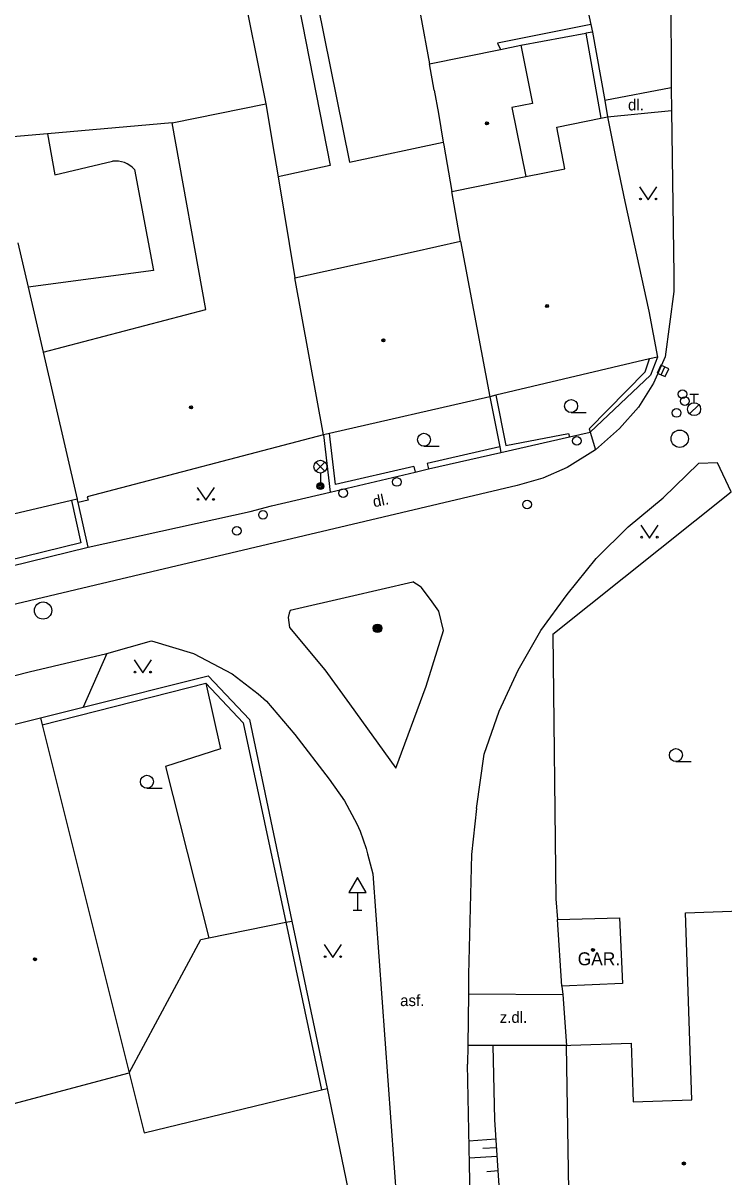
# Model space of a CAD drawing. Extents: x -596024 to -594475, y -1163820 to -1161957.
# Drawn here: x -595918.9 to -595878.3, y -1162976.4 to -1162909.7 of the extents above; entities that cross this region are included whole.
import ezdxf

# ---------------------------------------------------------------- set-up
doc = ezdxf.new("R2010")
doc.units = 0
for name, color, linetype in [('Level 10', 7, 'Continuous'), ('Level 11', 7, 'Continuous'), ('Level 14', 7, 'Continuous'), ('Level 15', 7, 'Continuous'), ('Level 25', 7, 'Continuous'), ('Level 27', 7, 'Continuous'), ('Level 28', 7, 'Continuous'), ('Level 33', 7, 'Continuous'), ('Level 34', 7, 'Continuous'), ('Level 36', 7, 'Continuous'), ('Level 39', 7, 'Continuous'), ('Level 40', 7, 'Continuous'), ('Level 41', 7, 'Continuous'), ('Level 5', 7, 'Continuous'), ('Level 7', 7, 'Continuous'), ('Level 8', 7, 'Continuous')]:
    doc.layers.add(name, color=color, linetype=linetype)

msp = doc.modelspace()

# ---------------------------------------------------------------- linework, layer by layer
at = {"layer": 'Level 10'}
for points in [[(-595881.44, -1162901.97), (-595881.4, -1162913.49)], [(-595881.4, -1162913.49), (-595881.38, -1162914.79)], [(-595881.38, -1162914.79), (-595881.25, -1162924.29)], [(-595881.25, -1162924.29), (-595881.24, -1162925.26), (-595881.74, -1162929.04)], [(-595881.74, -1162929.04), (-595882.41, -1162930.55), (-595883.29, -1162931.94), (-595884.38, -1162933.18), (-595885.77, -1162934.41)], [(-595885.77, -1162934.41), (-595887.41, -1162935.44), (-595888.81, -1162936.05)], [(-595877.93, -1162936.84), (-595878.71, -1162935.16), (-595879.82, -1162935.2), (-595881.85, -1162937.19)], [(-595888.81, -1162936.05), (-595890.3, -1162936.47), (-595913.55, -1162941.97)], [(-595892.66, -1162955.15), (-595892.21, -1162952), (-595891.34, -1162949.52), (-595890.24, -1162947.14), (-595888.94, -1162944.86), (-595887.41, -1162942.78), (-595885.74, -1162940.7), (-595883.88, -1162938.86), (-595881.85, -1162937.19)], [(-595913.55, -1162941.97), (-595928.03, -1162945.39)], [(-595903.434, -1162943.703), (-595903.477, -1162943.852), (-595903.553, -1162944.111), (-595903.464, -1162944.677), (-595901.427, -1162947.122), (-595900, -1162949.093), (-595897.312, -1162952.807), (-595895.563, -1162948.076), (-595894.569, -1162944.856), (-595894.828, -1162943.743), (-595895.315, -1162943.057), (-595895.851, -1162942.352), (-595895.913, -1162942.314), (-595896.34, -1162942.05)], [(-595896.338, -1162942.054), (-595900, -1162942.905), (-595903.434, -1162943.703)], [(-595914.04, -1162946.18), (-595911.45, -1162945.45)], [(-595911.45, -1162945.45), (-595909.02, -1162946.19), (-595906.78, -1162947.36), (-595905.27, -1162948.51), (-595904.8, -1162948.94), (-595903.15, -1162950.87)], [(-595918.53, -1162947.25), (-595914.04, -1162946.18)], [(-595926.31, -1162949.23), (-595918.53, -1162947.25)], [(-595903.15, -1162950.87), (-595901.17, -1162953.45)], [(-595901.17, -1162953.45), (-595900.29, -1162954.7), (-595899.58, -1162956.04), (-595899.39, -1162956.46), (-595899.03, -1162957.46), (-595898.95, -1162957.77), (-595898.65, -1162958.93)], [(-595892.66, -1162955.15), (-595892.94, -1162957.799), (-595893.11, -1162964.74)], [(-595898.65, -1162958.93), (-595897.09, -1162980.42)], [(-595893.11, -1162964.74), (-595893.12, -1162965.87), (-595893.16, -1162968.85), (-595893.17, -1162969.93)], [(-595892.69, -1162984.19), (-595893, -1162978.7), (-595893.06, -1162975.7), (-595893.17, -1162969.93)]]:
    msp.add_lwpolyline(points, dxfattribs=at)
at = {"layer": 'Level 11'}
for points in [[(-595907.81, -1162899.59), (-595904.83, -1162914.4)], [(-595904.74, -1162899.49), (-595901.11, -1162917.98), (-595904.13, -1162918.63)], [(-595903.7, -1162899.45), (-595899.99, -1162917.78), (-595894.58, -1162916.62)], [(-595895.89, -1162909.28), (-595895.38, -1162912.1)], [(-595886.04, -1162909.83), (-595891.43, -1162910.9), (-595891.26, -1162911.26)], [(-595890.09, -1162911.02), (-595886.34, -1162910.33)], [(-595881.4, -1162913.49), (-595885.24, -1162914.22)], [(-595885.07, -1162915.16), (-595881.38, -1162914.79)], [(-595910.26, -1162915.51), (-595917.46, -1162916.14), (-595920.37, -1162916.4)], [(-595917.46, -1162916.14), (-595917.04, -1162918.52), (-595913.71, -1162917.73)], [(-595912.44, -1162918.2), (-595911.33, -1162924.04), (-595918.58, -1162925.01)], [(-595882.18, -1162929.05), (-595882.6, -1162930.1)], [(-595891.88, -1162931.34), (-595891.31, -1162934.23)], [(-595901.5, -1162933.54), (-595901.11, -1162936.85)], [(-595886.08, -1162933.39), (-595885.77, -1162934.41)], [(-595891.31, -1162934.23), (-595891.24, -1162934.57)], [(-595895.42, -1162935.51), (-595891.24, -1162934.57)], [(-595901.11, -1162936.85), (-595896.2, -1162935.7)], [(-595904.51, -1162937.64), (-595901.11, -1162936.85)], [(-595916.07, -1162937.34), (-595915.54, -1162939.79), (-595927.34, -1162942.68), (-595927.97, -1162940.13)], [(-595915.11, -1162940.04), (-595915.68, -1162937.45)], [(-595928.31, -1162940.21), (-595927.6, -1162943.1), (-595915.11, -1162940.04)], [(-595914.04, -1162946.18), (-595915.4, -1162949.29)], [(-595908.3, -1162947.91), (-595907.45, -1162951.7), (-595910.63, -1162952.71), (-595908.14, -1162962.63)], [(-595893.12, -1162965.87), (-595887.67, -1162965.89)], [(-595887.44, -1162968.84), (-595891.69, -1162968.85), (-595893.16, -1162968.85)]]:
    msp.add_lwpolyline(points, dxfattribs=at)
msp.add_arc((-595913.511, -1162919.144), 1.428, 41.38561, 97.9975, dxfattribs=at)
at = {"layer": 'Level 14'}
msp.add_lwpolyline([(-595886.28, -1162985.95), (-595890.76, -1162985.73), (-595891.6, -1162973.14), (-595891.69, -1162968.85)], dxfattribs=at)
at = {"layer": 'Level 15'}
for points in [[(-595891.53, -1162974.26), (-595893.09, -1162974.37)], [(-595891.49, -1162974.76), (-595892.28, -1162974.81)], [(-595891.46, -1162975.26), (-595893.07, -1162975.37)], [(-595892.05, -1162976.13), (-595891.39, -1162976.08)]]:
    msp.add_lwpolyline(points, dxfattribs=at)
at = {"layer": 'Level 25'}
for radius in [0.25, 0.2, 0.15, 0.1, 0.05]:
    msp.add_circle((-595898.37, -1162944.73), radius, dxfattribs=at)
at = {"layer": 'Level 27'}
msp.add_line((-595881.971, -1162930.079), (-595881.769, -1162929.621), dxfattribs=at)
msp.add_lwpolyline([(-595881.742, -1162930.18), (-595881.54, -1162929.722), (-595881.998, -1162929.52), (-595882.2, -1162929.978)], close=True, dxfattribs=at)
for centre in [(-595880.9, -1162933.77), (-595917.72, -1162943.7)]:
    msp.add_circle(centre, 0.5, dxfattribs=at)
at = {"layer": 'Level 28'}
for p, q in [((-595880.32, -1162931.185), (-595879.82, -1162931.185)), ((-595880.07, -1162931.685), (-595880.07, -1162931.185)), ((-595880.328, -1162932.332), (-595879.798, -1162931.802))]:
    msp.add_line(p, q, dxfattribs=at)
for centre, radius in [((-595880.74, -1162931.19), 0.25), ((-595880.61, -1162931.59), 0.25), ((-595881.08, -1162932.28), 0.25), ((-595880.07, -1162932.06), 0.375), ((-595886.85, -1162933.89), 0.25), ((-595897.26, -1162936.27), 0.25), ((-595900.37, -1162936.91), 0.25), ((-595889.73, -1162937.57), 0.25), ((-595905, -1162938.17), 0.25), ((-595906.52, -1162939.09), 0.25)]:
    msp.add_circle(centre, radius, dxfattribs=at)
at = {"layer": 'Level 33'}
for p, q in [((-595901.945, -1162935.65), (-595901.415, -1162935.12)), ((-595901.945, -1162935.12), (-595901.415, -1162935.65)), ((-595901.68, -1162935.76), (-595901.68, -1162936.51))]:
    msp.add_line(p, q, dxfattribs=at)
for centre, radius in [((-595901.68, -1162935.385), 0.375), ((-595901.68, -1162936.51), 0.2), ((-595901.68, -1162936.51), 0.145), ((-595901.68, -1162936.51), 0.0876)]:
    msp.add_circle(centre, radius, dxfattribs=at)
at = {"layer": 'Level 34'}
for p, q in [((-595899.54, -1162960.002), (-595899.54, -1162961.02)), ((-595899.79, -1162961.02), (-595899.29, -1162961.02))]:
    msp.add_line(p, q, dxfattribs=at)
msp.add_lwpolyline([(-595900.04, -1162960.002), (-595899.04, -1162960.002), (-595899.54, -1162959.136)], close=True, dxfattribs=at)
at = {"layer": 'Level 36'}
for p, q in [((-595887.18, -1162932.255), (-595886.305, -1162932.255)), ((-595895.69, -1162934.205), (-595894.815, -1162934.205)), ((-595881.12, -1162952.435), (-595880.245, -1162952.435)), ((-595911.71, -1162953.975), (-595910.835, -1162953.975))]:
    msp.add_line(p, q, dxfattribs=at)
for points in [[(-595883.22, -1162919.21), (-595882.72, -1162919.96), (-595882.22, -1162919.21)], [(-595908.81, -1162936.58), (-595908.31, -1162937.33), (-595907.81, -1162936.58)], [(-595883.15, -1162938.76), (-595882.65, -1162939.51), (-595882.15, -1162938.76)], [(-595912.45, -1162946.56), (-595911.95, -1162947.31), (-595911.45, -1162946.56)], [(-595901.46, -1162963.01), (-595900.96, -1162963.76), (-595900.46, -1162963.01)]]:
    msp.add_lwpolyline(points, dxfattribs=at)
for centre, radius in [((-595883.17, -1162919.91), 0.05), ((-595882.271, -1162919.91), 0.05), ((-595887.18, -1162931.88), 0.375), ((-595895.69, -1162933.83), 0.375), ((-595908.76, -1162937.28), 0.05), ((-595907.861, -1162937.28), 0.05), ((-595883.1, -1162939.46), 0.05), ((-595882.201, -1162939.46), 0.05), ((-595912.4, -1162947.26), 0.05), ((-595911.501, -1162947.26), 0.05), ((-595881.12, -1162952.06), 0.375), ((-595911.71, -1162953.6), 0.375), ((-595901.41, -1162963.71), 0.05), ((-595900.511, -1162963.71), 0.05)]:
    msp.add_circle(centre, radius, dxfattribs=at)
at = {"layer": 'Level 39'}
for centre, radius in [((-595892.05, -1162915.54), 0.09), ((-595892.05, -1162915.54), 0.0398), ((-595888.57, -1162926.1), 0.09), ((-595888.57, -1162926.1), 0.0398), ((-595898.04, -1162928.08), 0.09), ((-595898.04, -1162928.08), 0.0398), ((-595909.16, -1162931.96), 0.09), ((-595909.16, -1162931.96), 0.0398), ((-595885.92, -1162963.32), 0.09), ((-595885.92, -1162963.32), 0.0398), ((-595918.19, -1162963.86), 0.09), ((-595918.19, -1162963.86), 0.0398), ((-595880.66, -1162975.67), 0.09), ((-595880.66, -1162975.67), 0.0398)]:
    msp.add_circle(centre, radius, dxfattribs=at)
at = {"layer": 'Level 5'}
for points in [[(-595895.38, -1162912.1), (-595891.26, -1162911.26)], [(-595891.26, -1162911.26), (-595890.09, -1162911.02)], [(-595890.09, -1162911.02), (-595889.41, -1162914.39)], [(-595895.11, -1162913.62), (-595895.38, -1162912.1)], [(-595895.11, -1162913.62), (-595894.86, -1162914.96)], [(-595910.26, -1162915.51), (-595904.83, -1162914.4)], [(-595904.83, -1162914.4), (-595904.36, -1162917.28)], [(-595889.41, -1162914.39), (-595890.61, -1162914.63)], [(-595890.61, -1162914.63), (-595889.8, -1162918.61)], [(-595908.3, -1162926.3), (-595910.26, -1162915.51)], [(-595894.86, -1162914.96), (-595894.58, -1162916.62), (-595894.55, -1162916.79)], [(-595888.01, -1162915.76), (-595885.46, -1162915.24)], [(-595885.46, -1162915.24), (-595885.07, -1162915.16)], [(-595885.07, -1162915.16), (-595884.59, -1162917.56)], [(-595887.54, -1162918.16), (-595888.01, -1162915.76)], [(-595894.55, -1162916.79), (-595894.07, -1162919.47)], [(-595904.36, -1162917.28), (-595904.13, -1162918.63), (-595903.16, -1162924.46)], [(-595884.59, -1162917.56), (-595884.07, -1162920.06)], [(-595889.8, -1162918.61), (-595887.54, -1162918.16)], [(-595894.07, -1162919.47), (-595889.8, -1162918.61)], [(-595893.57, -1162922.35), (-595894.07, -1162919.47)], [(-595884.07, -1162920.06), (-595882.69, -1162926.39)], [(-595919.17, -1162922.45), (-595918.58, -1162925.01), (-595917.71, -1162928.76)], [(-595903.16, -1162924.46), (-595896.32, -1162922.96)], [(-595896.32, -1162922.96), (-595893.57, -1162922.35)], [(-595893.57, -1162922.35), (-595891.88, -1162931.34)], [(-595901.5, -1162933.54), (-595903.16, -1162924.46)], [(-595917.71, -1162928.76), (-595908.3, -1162926.3)], [(-595882.69, -1162926.39), (-595882.18, -1162929.05)], [(-595917.71, -1162928.76), (-595915.74, -1162937.26)], [(-595882.65, -1162929.15), (-595891.54, -1162931.26)], [(-595882.18, -1162929.05), (-595882.65, -1162929.15)], [(-595891.88, -1162931.34), (-595901.16, -1162933.46)], [(-595891.54, -1162931.26), (-595891.88, -1162931.34)], [(-595901.5, -1162933.54), (-595915.16, -1162937.12)], [(-595901.16, -1162933.46), (-595901.5, -1162933.54)], [(-595916.07, -1162937.34), (-595927.97, -1162940.13)], [(-595915.74, -1162937.26), (-595916.07, -1162937.34)], [(-595915.68, -1162937.45), (-595915.74, -1162937.26)], [(-595915.12, -1162937.32), (-595915.68, -1162937.45)], [(-595915.16, -1162937.12), (-595915.12, -1162937.32)], [(-595925.45, -1162951.8), (-595917.87, -1162949.91)], [(-595917.87, -1162949.91), (-595917.77, -1162950.3)], [(-595917.77, -1162950.3), (-595912.73, -1162970.43)], [(-595887.97, -1162961.56), (-595884.38, -1162961.46)], [(-595887.71, -1162965.42), (-595887.97, -1162961.56)], [(-595884.38, -1162961.46), (-595884.21, -1162965.26)], [(-595880.57, -1162961.18), (-595877.37, -1162961.07)], [(-595880.21, -1162971.99), (-595880.57, -1162961.18)], [(-595884.21, -1162965.26), (-595887.71, -1162965.42)], [(-595887.44, -1162968.84), (-595887.19, -1162968.83)], [(-595887.24, -1162982.04), (-595887.44, -1162968.84)], [(-595887.19, -1162968.83), (-595883.71, -1162968.72)], [(-595883.71, -1162968.72), (-595883.6, -1162972.1)], [(-595920.36, -1162972.45), (-595912.73, -1162970.43)], [(-595912.73, -1162970.43), (-595911.87, -1162973.9)], [(-595911.87, -1162973.9), (-595901.61, -1162971.41)], [(-595901.61, -1162971.41), (-595901.29, -1162971.33)], [(-595901.29, -1162971.33), (-595899.6, -1162979.55)], [(-595883.6, -1162972.1), (-595880.21, -1162971.99)]]:
    msp.add_lwpolyline(points, dxfattribs=at)
at = {"layer": 'Level 7'}
for points in [[(-595887.83, -1162901.57), (-595886.04, -1162909.83)], [(-595885.95, -1162910.26), (-595886.34, -1162910.33)], [(-595886.04, -1162909.83), (-595885.95, -1162910.26)], [(-595885.95, -1162910.26), (-595885.24, -1162914.22), (-595885.07, -1162915.16)], [(-595886.34, -1162910.33), (-595885.46, -1162915.24)], [(-595886.13, -1162933.19), (-595882.9, -1162929.9), (-595882.65, -1162929.15)], [(-595886.08, -1162933.39), (-595882.6, -1162930.1)], [(-595891.54, -1162931.26), (-595890.96, -1162934.16), (-595887.34, -1162933.47)], [(-595900.81, -1162936.42), (-595901.16, -1162933.46)], [(-595887.34, -1162933.47), (-595887.27, -1162933.66)], [(-595886.13, -1162933.19), (-595886.08, -1162933.39)], [(-595891.31, -1162934.23), (-595895.5, -1162935.2)], [(-595891.24, -1162934.57), (-595887.27, -1162933.66)], [(-595896.27, -1162935.38), (-595900.81, -1162936.42)], [(-595896.27, -1162935.38), (-595896.2, -1162935.7)], [(-595895.5, -1162935.2), (-595895.42, -1162935.51)], [(-595888.24, -1162945.07), (-595877.93, -1162936.84)], [(-595915.11, -1162940.04), (-595905.74, -1162937.97)], [(-595888.24, -1162945.07), (-595888.06, -1162960.36)], [(-595917.87, -1162949.91), (-595915.4, -1162949.29), (-595908.17, -1162947.47), (-595905.78, -1162950), (-595903.34, -1162961.65)], [(-595917.77, -1162950.3), (-595908.3, -1162947.91), (-595906.15, -1162950.19), (-595903.68, -1162961.72)], [(-595903.68, -1162961.72), (-595903.34, -1162961.65)], [(-595903.34, -1162961.65), (-595901.29, -1162971.33)], [(-595912.73, -1162970.43), (-595908.6, -1162962.72), (-595908.14, -1162962.63), (-595903.68, -1162961.72)], [(-595903.68, -1162961.72), (-595901.61, -1162971.41)]]:
    msp.add_lwpolyline(points, dxfattribs=at)
at = {"layer": 'Level 8'}
for points in [[(-595887.27, -1162933.66), (-595886.08, -1162933.39)], [(-595896.2, -1162935.7), (-595895.42, -1162935.51)], [(-595905.74, -1162937.97), (-595904.51, -1162937.64)], [(-595888.06, -1162960.36), (-595887.97, -1162961.56)], [(-595887.71, -1162965.42), (-595887.67, -1162965.89), (-595887.44, -1162968.84)]]:
    msp.add_lwpolyline(points, dxfattribs=at)

# ---------------------------------------------------------------- texts
at = {"layer": 'Level 40'}
for s, p in [('dl.', (-595883.89, -1162914.79)), ('asf.', (-595897.07, -1162966.57)), ('z.dl.', (-595891.31, -1162967.54))]:
    msp.add_text(s, height=0.65, dxfattribs=at).set_placement(p)
msp.add_text('dl.', height=0.65, rotation=12, dxfattribs=at).set_placement((-595898.58, -1162937.74))
at = {"layer": 'Level 41'}
msp.add_text('GAR.', height=0.75, dxfattribs=at).set_placement((-595886.8, -1162964.21))

doc.saveas('drawing.dxf')
